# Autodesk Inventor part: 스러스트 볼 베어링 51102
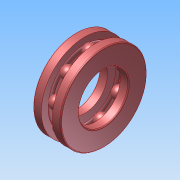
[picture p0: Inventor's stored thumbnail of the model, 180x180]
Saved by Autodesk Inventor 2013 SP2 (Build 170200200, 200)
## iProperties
Created: 2025-09
Part Number: 스러스트 볼 베어링 51102
Material: Generic
Document SubType Name: Modeling
Designer: a
Density: 1 g/cm^3
Author: a
변환 표준: STEP AP214IS
전처리기: Build: 200, Release: 2013 SP2 Update 6 - Date: Thu 07/17/2014
전송 단위: 밀리미터
불확실성: 0.01
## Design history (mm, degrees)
node "스러스트 볼 베어링 511021"
body "Solid1"
node "Solid1_1"
node "Solid1_2"
node "Solid1_3"
node "Solid1_4"
node "Solid1_5"
node "Solid1_6"
node "Solid1_7"
node "Solid1_8"
node "Solid1_9"
node "Solid1_10"
node "기준1"
node "기준2"
node "기준3"
node "기준4"
node "기준5"
node "기준6"
node "기준7"
node "기준8"
node "기준9"
node "기준10"
node "기준11"
